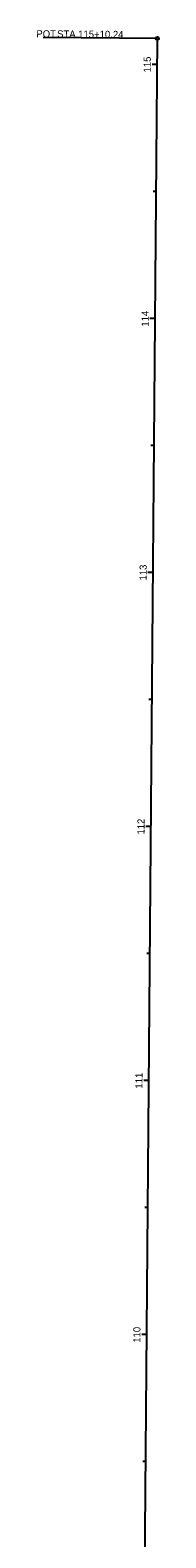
# Model space of a CAD drawing. Extents: x 217610 to 217676, y 457884 to 460293.
# Drawn here: x 217628 to 217676, y 459699 to 460293 of the extents above; entities that cross this region are included whole.
import ezdxf

# ---------------------------------------------------------------- set-up
doc = ezdxf.new("R2010")
doc.units = 0
for name, color, linetype in [('RW_X_CL', 7, 'Continuous'), ('RW_X_CL_100_Cardinal_Points', 7, 'Continuous'), ('RW_X_CL_100_Stations', 7, 'Continuous'), ('RW_X_CL_500_Cardinal_Points', 7, 'Continuous'), ('RW_X_CL_500_Stations', 7, 'Continuous')]:
    doc.layers.add(name, color=color, linetype=linetype)

msp = doc.modelspace()

# ---------------------------------------------------------------- linework, layer by layer
at = {"layer": 'RW_X_CL'}
msp.add_line((217663.13, 458779.17), (217675.43, 460289.35), dxfattribs=at)
at = {"layer": 'RW_X_CL_100_Cardinal_Points'}
msp.add_line((217675.43, 460289.35), (217630.43, 460289.72), dxfattribs=at)
msp.add_circle((217675.43, 460289.35), 0.6, dxfattribs=at)
at = {"layer": 'RW_X_CL_100_Stations'}
for p, q in [((217675.34, 460279.12), (217673.34, 460279.13)), ((217674.93, 460229.12), (217673.74, 460229.13)), ((217674.53, 460179.12), (217672.53, 460179.14)), ((217674.12, 460129.12), (217672.92, 460129.13)), ((217673.71, 460079.12), (217671.71, 460079.14)), ((217673.31, 460029.12), (217672.11, 460029.13)), ((217672.9, 459979.13), (217670.9, 459979.14)), ((217672.49, 459929.13), (217671.29, 459929.14)), ((217672.09, 459879.13), (217670.09, 459879.15)), ((217671.68, 459829.13), (217670.48, 459829.14)), ((217671.27, 459779.13), (217669.27, 459779.15)), ((217670.87, 459729.13), (217669.67, 459729.14))]:
    msp.add_line(p, q, dxfattribs=at)
at = {"layer": 'RW_X_CL_500_Cardinal_Points'}
msp.add_line((217675.43, 460289.35), (217630.43, 460289.72), dxfattribs=at)
msp.add_circle((217675.43, 460289.35), 0.6, dxfattribs=at)
at = {"layer": 'RW_X_CL_500_Stations'}
for p, q in [((217675.34, 460279.12), (217673.34, 460279.13)), ((217674.53, 460179.12), (217673.33, 460179.13)), ((217673.71, 460079.12), (217672.51, 460079.13)), ((217672.9, 459979.13), (217671.7, 459979.14)), ((217672.09, 459879.13), (217670.89, 459879.14)), ((217671.27, 459779.13), (217669.27, 459779.15))]:
    msp.add_line(p, q, dxfattribs=at)

# ---------------------------------------------------------------- texts
at = {"layer": 'RW_X_CL_100_Cardinal_Points'}
for s, p in [('POT', (217627.81, 460289.78)), (' STA. ', (217634.94, 460289.72)), ('115+10.24', (217644.27, 460289.64))]:
    msp.add_text(s, height=2.8, rotation=359.53369, dxfattribs=at).set_placement(p)
at = {"layer": 'RW_X_CL_100_Stations'}
for s, p in [('115', (217672.82, 460275.93)), ('114', (217672, 460175.86)), ('113', (217671.19, 460075.95)), ('112', (217670.37, 459975.94)), ('111', (217669.56, 459875.93)), ('110', (217668.75, 459775.89))]:
    msp.add_text(s, height=2.8, rotation=89.53369, dxfattribs=at).set_placement(p)
at = {"layer": 'RW_X_CL_500_Cardinal_Points'}
for s, p in [('POT', (217627.81, 460289.78)), (' STA. ', (217634.94, 460289.72)), ('115+10.24', (217644.27, 460289.64))]:
    msp.add_text(s, height=2.8, rotation=359.53369, dxfattribs=at).set_placement(p)
at = {"layer": 'RW_X_CL_500_Stations'}
for s, p in [('115', (217672.82, 460275.93)), ('110', (217668.75, 459775.89))]:
    msp.add_text(s, height=2.8, rotation=89.53369, dxfattribs=at).set_placement(p)

doc.saveas('drawing.dxf')
